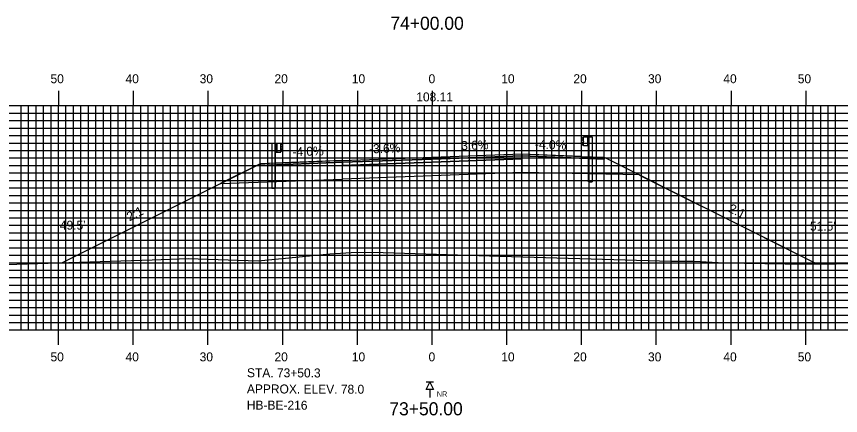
# Model space of a CAD drawing. Extents: x 1761004 to 1761347, y 442591 to 442811.
# Drawn here: x 1761114.1 to 1761224.4, y 442647.2 to 442700.6 of the extents above; entities that cross this region are included whole.
import ezdxf

# ---------------------------------------------------------------- set-up
doc = ezdxf.new("R2010")
doc.units = 0
for name, color, linetype in [('ANNOTATION', 7, 'Continuous'), ('BORING - NO REFUSAL', 7, 'Continuous'), ('D_Guardrail_Beam_Lt', 7, 'Continuous'), ('D_Guardrail_Beam_Rt', 7, 'Continuous'), ('D_Roadway_Centerline', 7, 'Continuous'), ('D_Roadway_Centerline_Text', 7, 'Continuous'), ('D_Roadway_Edge_Shoulder', 7, 'Continuous'), ('D_Roadway_Edge_TW', 7, 'Continuous'), ('D_Roadway_Pavement', 7, 'Continuous'), ('D_Roadway_SlopeLines', 7, 'Continuous'), ('D_Roadway_SubGrade', 7, 'Continuous'), ('D_Text_Standard', 7, 'Continuous'), ('H_V ANNOTATION', 7, 'Continuous'), ('MAJOR', 7, 'Continuous'), ('MINOR', 7, 'Continuous'), ('S_Roadway_Centerline', 7, 'Continuous')]:
    doc.layers.add(name, color=color, linetype=linetype)

msp = doc.modelspace()

# ---------------------------------------------------------------- linework, layer by layer
at = {"layer": 'BORING - NO REFUSAL'}
for p, q in [((1761169.91, 442651.67), (1761168.95, 442651.67)), ((1761169.43, 442650.71), (1761169.43, 442649.65))]:
    msp.add_line(p, q, dxfattribs=at)
msp.add_lwpolyline([(1761169.43, 442651.67), (1761169.91, 442650.71), (1761168.95, 442650.71)], close=True, dxfattribs=at)
at = {"layer": 'D_Guardrail_Beam_Lt'}
for p, q in [((1761148.3, 442683.61), (1761148.3, 442677.61)), ((1761148.77, 442683.61), (1761148.3, 442683.61)), ((1761149.46, 442683.61), (1761148.77, 442683.61)), ((1761148.77, 442683.61), (1761148.77, 442682.44)), ((1761148.83, 442683.61), (1761148.83, 442682.44)), ((1761148.94, 442683.61), (1761148.94, 442682.44)), ((1761149.46, 442682.44), (1761149.46, 442683.61)), ((1761149.46, 442683.53), (1761149.53, 442683.51)), ((1761149.46, 442683.06), (1761149.46, 442682.99)), ((1761149.69, 442683.26), (1761149.49, 442683.13)), ((1761149.49, 442682.93), (1761149.69, 442682.79)), ((1761149.55, 442683.51), (1761149.69, 442683.41)), ((1761148.77, 442682.44), (1761149.46, 442682.44)), ((1761148.79, 442677.61), (1761148.79, 442682.44)), ((1761149.53, 442682.54), (1761149.46, 442682.53)), ((1761149.69, 442682.65), (1761149.55, 442682.55)), ((1761148.79, 442677.61), (1761148.3, 442677.61))]:
    msp.add_line(p, q, dxfattribs=at)
for centre, major_axis, start_param, end_param in [((1761149.54, 442683.06), (-0.0789, 0), 5.323254, 6.283185), ((1761149.54, 442682.99), (-0.0789, 0), 6.283185, 7.243116), ((1761149.52, 442683.47), (0.0417, 0), 0.959931, 1.376053), ((1761149.64, 442683.34), (0.0877, 0), 5.323254, 7.243116), ((1761149.52, 442682.58), (0.0417, 0), 4.907132, 5.323254), ((1761149.64, 442682.72), (0.0877, 0), 5.323254, 7.243116)]:
    msp.add_ellipse(centre, major_axis=major_axis, ratio=0.995501, start_param=start_param, end_param=end_param, dxfattribs=at)
at = {"layer": 'D_Guardrail_Beam_Rt'}
for p, q in [((1761189.91, 442684.37), (1761189.76, 442684.27)), ((1761189.76, 442684.13), (1761189.96, 442683.99)), ((1761190, 442684.39), (1761189.92, 442684.38)), ((1761190, 442684.48), (1761190.69, 442684.48)), ((1761190, 442683.31), (1761190, 442684.48)), ((1761190.52, 442684.48), (1761190.52, 442683.31)), ((1761190.62, 442684.48), (1761190.62, 442683.31)), ((1761190.69, 442684.48), (1761191.16, 442684.48)), ((1761190.69, 442684.48), (1761190.69, 442683.31)), ((1761191.16, 442684.48), (1761191.16, 442678.48)), ((1761189.96, 442683.79), (1761189.76, 442683.66)), ((1761189.76, 442683.51), (1761189.91, 442683.41)), ((1761189.92, 442683.41), (1761190, 442683.39)), ((1761189.99, 442683.93), (1761189.99, 442683.86)), ((1761190.69, 442683.31), (1761190, 442683.31)), ((1761190.66, 442678.48), (1761190.66, 442683.31)), ((1761190.66, 442678.48), (1761191.16, 442678.48))]:
    msp.add_line(p, q, dxfattribs=at)
for centre, major_axis, start_param, end_param in [((1761189.81, 442684.2), (-0.0877, 0), 5.323254, 7.243116), ((1761189.93, 442684.34), (-0.0417, 0), 4.907132, 5.323254), ((1761189.81, 442683.59), (-0.0877, 0), 5.323254, 7.243116), ((1761189.93, 442683.45), (-0.0417, 0), 0.959931, 1.376053), ((1761189.91, 442683.93), (0.0789, 0), 0, 0.959931), ((1761189.91, 442683.86), (0.0789, 0), 5.323254, 6.283185)]:
    msp.add_ellipse(centre, major_axis=major_axis, ratio=0.995501, start_param=start_param, end_param=end_param, dxfattribs=at)
at = {"layer": 'D_Roadway_Centerline'}
msp.add_lwpolyline([(1761120.24, 442667.66), (1761120.72, 442667.91), (1761141.42, 442678.25), (1761141.43, 442678.26), (1761141.44, 442678.26), (1761145.72, 442680.4), (1761146.73, 442680.91), (1761147.95, 442680.96), (1761149.73, 442681.03), (1761149.73, 442681.03), (1761157.1, 442681.32), (1761157.73, 442681.35), (1761169.73, 442681.78), (1761169.73, 442681.78), (1761181.73, 442682.21), (1761181.73, 442682.21), (1761189.63, 442681.9), (1761189.73, 442681.89), (1761192.73, 442681.77), (1761192.73, 442681.77), (1761197.48, 442679.4), (1761197.49, 442679.39), (1761214.48, 442670.9), (1761221.22, 442667.52), (1761221.23, 442667.52)], dxfattribs=at)
at = {"layer": 'D_Roadway_Edge_Shoulder'}
for points in [[(1761181.73, 442682.21), (1761189.73, 442681.89), (1761189.73, 442681.89), (1761192.73, 442681.77), (1761192.73, 442681.52), (1761181.73, 442681.96)], [(1761157.73, 442681.35), (1761149.73, 442681.03), (1761149.73, 442681.03), (1761146.73, 442680.91), (1761146.73, 442680.66), (1761157.73, 442681.1)]]:
    msp.add_lwpolyline(points, close=True, dxfattribs=at)
at = {"layer": 'D_Roadway_Edge_TW'}
msp.add_lwpolyline([(1761157.73, 442681.1), (1761157.73, 442681.35), (1761169.73, 442681.78), (1761181.73, 442682.21), (1761181.73, 442681.96), (1761169.73, 442681.53)], close=True, dxfattribs=at)
at = {"layer": 'D_Roadway_Pavement'}
msp.add_lwpolyline([(1761157.73, 442680.68), (1761157.73, 442681.1), (1761169.73, 442681.53), (1761181.73, 442681.96), (1761181.73, 442681.55), (1761169.73, 442681.11)], close=True, dxfattribs=at)
for points in [[(1761181.73, 442681.96), (1761181.73, 442681.55)], [(1761157.73, 442681.1), (1761157.73, 442680.68)]]:
    msp.add_lwpolyline(points, dxfattribs=at)
at = {"layer": 'D_Roadway_SlopeLines'}
for points in [[(1761146.73, 442680.91), (1761120.24, 442667.66)], [(1761192.73, 442681.77), (1761221.23, 442667.52)]]:
    msp.add_lwpolyline(points, dxfattribs=at)
at = {"layer": 'D_Roadway_SubGrade'}
for points in [[(1761157.73, 442678.85), (1761157.73, 442681.1), (1761157.73, 442680.68), (1761169.73, 442681.11), (1761181.73, 442681.55), (1761181.73, 442681.96), (1761181.73, 442679.71), (1761169.73, 442679.28)], [(1761181.73, 442681.55), (1761181.73, 442681.96), (1761192.73, 442681.52), (1761192.73, 442681.77), (1761197.48, 442679.4), (1761181.73, 442679.71)], [(1761157.73, 442680.68), (1761157.73, 442681.1), (1761146.73, 442680.66), (1761146.73, 442680.91), (1761141.43, 442678.26), (1761157.73, 442678.85)]]:
    msp.add_lwpolyline(points, close=True, dxfattribs=at)
at = {"layer": 'MAJOR'}
for p, q in [((1761119.73, 442690.67), (1761119.73, 442688.67)), ((1761129.73, 442690.67), (1761129.73, 442688.67)), ((1761139.73, 442690.67), (1761139.73, 442688.67)), ((1761149.73, 442690.67), (1761149.73, 442688.67)), ((1761159.73, 442690.67), (1761159.73, 442688.67)), ((1761169.73, 442690.67), (1761169.73, 442688.67)), ((1761179.73, 442690.67), (1761179.73, 442688.67)), ((1761189.73, 442690.67), (1761189.73, 442688.67)), ((1761199.73, 442690.67), (1761199.73, 442688.67)), ((1761209.73, 442690.67), (1761209.73, 442688.67)), ((1761219.73, 442690.67), (1761219.73, 442688.67)), ((1761029.73, 442688.67), (1761309.73, 442688.67)), ((1761029.73, 442688.67), (1761309.73, 442688.67)), ((1761119.73, 442658.67), (1761119.73, 442688.67)), ((1761129.73, 442658.67), (1761129.73, 442688.67)), ((1761139.73, 442658.67), (1761139.73, 442688.67)), ((1761149.73, 442658.67), (1761149.73, 442688.67)), ((1761159.73, 442658.67), (1761159.73, 442688.67)), ((1761169.73, 442658.67), (1761169.73, 442688.67)), ((1761179.73, 442658.67), (1761179.73, 442688.67)), ((1761189.73, 442658.67), (1761189.73, 442688.67)), ((1761199.73, 442658.67), (1761199.73, 442688.67)), ((1761209.73, 442658.67), (1761209.73, 442688.67)), ((1761219.73, 442658.67), (1761219.73, 442688.67)), ((1761029.73, 442683.67), (1761309.73, 442683.67)), ((1761029.73, 442678.67), (1761309.73, 442678.67)), ((1761029.73, 442673.67), (1761309.73, 442673.67)), ((1761029.73, 442668.67), (1761309.73, 442668.67)), ((1761029.73, 442663.67), (1761309.73, 442663.67)), ((1761029.73, 442658.67), (1761309.73, 442658.67)), ((1761029.73, 442658.67), (1761309.73, 442658.67)), ((1761119.73, 442656.66), (1761119.73, 442658.67)), ((1761129.73, 442656.66), (1761129.73, 442658.67)), ((1761139.73, 442656.66), (1761139.73, 442658.67)), ((1761149.73, 442656.66), (1761149.73, 442658.67)), ((1761159.73, 442656.66), (1761159.73, 442658.67)), ((1761169.73, 442656.66), (1761169.73, 442658.67)), ((1761179.73, 442656.66), (1761179.73, 442658.67)), ((1761189.73, 442656.66), (1761189.73, 442658.67)), ((1761199.73, 442656.66), (1761199.73, 442658.67)), ((1761209.73, 442656.66), (1761209.73, 442658.67)), ((1761219.73, 442656.66), (1761219.73, 442658.67))]:
    msp.add_line(p, q, dxfattribs=at)
at = {"layer": 'MINOR'}
for p, q in [((1761114.73, 442658.67), (1761114.73, 442688.67)), ((1761115.73, 442658.67), (1761115.73, 442688.67)), ((1761116.73, 442658.67), (1761116.73, 442688.67)), ((1761117.73, 442658.67), (1761117.73, 442688.67)), ((1761118.73, 442658.67), (1761118.73, 442688.67)), ((1761120.73, 442658.67), (1761120.73, 442688.67)), ((1761121.73, 442658.67), (1761121.73, 442688.67)), ((1761122.73, 442658.67), (1761122.73, 442688.67)), ((1761123.73, 442658.67), (1761123.73, 442688.67)), ((1761124.73, 442658.67), (1761124.73, 442688.67)), ((1761125.73, 442658.67), (1761125.73, 442688.67)), ((1761126.73, 442658.67), (1761126.73, 442688.67)), ((1761127.73, 442658.67), (1761127.73, 442688.67)), ((1761128.73, 442658.67), (1761128.73, 442688.67)), ((1761130.73, 442658.67), (1761130.73, 442688.67)), ((1761131.73, 442658.67), (1761131.73, 442688.67)), ((1761132.73, 442658.67), (1761132.73, 442688.67)), ((1761133.73, 442658.67), (1761133.73, 442688.67)), ((1761134.73, 442658.67), (1761134.73, 442688.67)), ((1761135.73, 442658.67), (1761135.73, 442688.67)), ((1761136.73, 442658.67), (1761136.73, 442688.67)), ((1761137.73, 442658.67), (1761137.73, 442688.67)), ((1761138.73, 442658.67), (1761138.73, 442688.67)), ((1761140.73, 442658.67), (1761140.73, 442688.67)), ((1761141.73, 442658.67), (1761141.73, 442688.67)), ((1761142.73, 442658.67), (1761142.73, 442688.67)), ((1761143.73, 442658.67), (1761143.73, 442688.67)), ((1761144.73, 442658.67), (1761144.73, 442688.67)), ((1761145.73, 442658.67), (1761145.73, 442688.67)), ((1761146.73, 442658.67), (1761146.73, 442688.67)), ((1761147.73, 442658.67), (1761147.73, 442688.67)), ((1761148.73, 442658.67), (1761148.73, 442688.67)), ((1761150.73, 442658.67), (1761150.73, 442688.67)), ((1761151.73, 442658.67), (1761151.73, 442688.67)), ((1761152.73, 442658.67), (1761152.73, 442688.67)), ((1761153.73, 442658.67), (1761153.73, 442688.67)), ((1761154.73, 442658.67), (1761154.73, 442688.67)), ((1761155.73, 442658.67), (1761155.73, 442688.67)), ((1761156.73, 442658.67), (1761156.73, 442688.67)), ((1761157.73, 442658.67), (1761157.73, 442688.67)), ((1761158.73, 442658.67), (1761158.73, 442688.67)), ((1761160.73, 442658.67), (1761160.73, 442688.67)), ((1761161.73, 442658.67), (1761161.73, 442688.67)), ((1761162.73, 442658.67), (1761162.73, 442688.67)), ((1761163.73, 442658.67), (1761163.73, 442688.67)), ((1761164.73, 442658.67), (1761164.73, 442688.67)), ((1761165.73, 442658.67), (1761165.73, 442688.67)), ((1761166.73, 442658.67), (1761166.73, 442688.67)), ((1761167.73, 442658.67), (1761167.73, 442688.67)), ((1761168.73, 442658.67), (1761168.73, 442688.67)), ((1761170.73, 442658.67), (1761170.73, 442688.67)), ((1761171.73, 442658.67), (1761171.73, 442688.67)), ((1761172.73, 442658.67), (1761172.73, 442688.67)), ((1761173.73, 442658.67), (1761173.73, 442688.67)), ((1761174.73, 442658.67), (1761174.73, 442688.67)), ((1761175.73, 442658.67), (1761175.73, 442688.67)), ((1761176.73, 442658.67), (1761176.73, 442688.67)), ((1761177.73, 442658.67), (1761177.73, 442688.67)), ((1761178.73, 442658.67), (1761178.73, 442688.67)), ((1761180.73, 442658.67), (1761180.73, 442688.67)), ((1761181.73, 442658.67), (1761181.73, 442688.67)), ((1761182.73, 442658.67), (1761182.73, 442688.67)), ((1761183.73, 442658.67), (1761183.73, 442688.67)), ((1761184.73, 442658.67), (1761184.73, 442688.67)), ((1761185.73, 442658.67), (1761185.73, 442688.67)), ((1761186.73, 442658.67), (1761186.73, 442688.67)), ((1761187.73, 442658.67), (1761187.73, 442688.67)), ((1761188.73, 442658.67), (1761188.73, 442688.67)), ((1761190.73, 442658.67), (1761190.73, 442688.67)), ((1761191.73, 442658.67), (1761191.73, 442688.67)), ((1761192.73, 442658.67), (1761192.73, 442688.67)), ((1761193.73, 442658.67), (1761193.73, 442688.67)), ((1761194.73, 442658.67), (1761194.73, 442688.67)), ((1761195.73, 442658.67), (1761195.73, 442688.67)), ((1761196.73, 442658.67), (1761196.73, 442688.67)), ((1761197.73, 442658.67), (1761197.73, 442688.67)), ((1761198.73, 442658.67), (1761198.73, 442688.67)), ((1761200.73, 442658.67), (1761200.73, 442688.67)), ((1761201.73, 442658.67), (1761201.73, 442688.67)), ((1761202.73, 442658.67), (1761202.73, 442688.67)), ((1761203.73, 442658.67), (1761203.73, 442688.67)), ((1761204.73, 442658.67), (1761204.73, 442688.67)), ((1761205.73, 442658.67), (1761205.73, 442688.67)), ((1761206.73, 442658.67), (1761206.73, 442688.67)), ((1761207.73, 442658.67), (1761207.73, 442688.67)), ((1761208.73, 442658.67), (1761208.73, 442688.67)), ((1761210.73, 442658.67), (1761210.73, 442688.67)), ((1761211.73, 442658.67), (1761211.73, 442688.67)), ((1761212.73, 442658.67), (1761212.73, 442688.67)), ((1761213.73, 442658.67), (1761213.73, 442688.67)), ((1761214.73, 442658.67), (1761214.73, 442688.67)), ((1761215.73, 442658.67), (1761215.73, 442688.67)), ((1761216.73, 442658.67), (1761216.73, 442688.67)), ((1761217.73, 442658.67), (1761217.73, 442688.67)), ((1761218.73, 442658.67), (1761218.73, 442688.67)), ((1761220.73, 442658.67), (1761220.73, 442688.67)), ((1761221.73, 442658.67), (1761221.73, 442688.67)), ((1761222.73, 442658.67), (1761222.73, 442688.67)), ((1761223.73, 442658.67), (1761223.73, 442688.67)), ((1761029.73, 442687.67), (1761309.73, 442687.67)), ((1761029.73, 442686.67), (1761309.73, 442686.67)), ((1761029.73, 442685.67), (1761309.73, 442685.67)), ((1761029.73, 442684.67), (1761309.73, 442684.67)), ((1761029.73, 442682.67), (1761309.73, 442682.67)), ((1761029.73, 442681.67), (1761309.73, 442681.67)), ((1761029.73, 442680.67), (1761309.73, 442680.67)), ((1761029.73, 442679.67), (1761309.73, 442679.67)), ((1761029.73, 442677.67), (1761309.73, 442677.67)), ((1761029.73, 442676.67), (1761309.73, 442676.67)), ((1761029.73, 442675.67), (1761309.73, 442675.67)), ((1761029.73, 442674.67), (1761309.73, 442674.67)), ((1761029.73, 442672.67), (1761309.73, 442672.67)), ((1761029.73, 442671.67), (1761309.73, 442671.67)), ((1761029.73, 442670.67), (1761309.73, 442670.67)), ((1761029.73, 442669.67), (1761309.73, 442669.67)), ((1761029.73, 442667.67), (1761309.73, 442667.67)), ((1761029.73, 442666.67), (1761309.73, 442666.67)), ((1761029.73, 442665.67), (1761309.73, 442665.67)), ((1761029.73, 442664.67), (1761309.73, 442664.67)), ((1761029.73, 442662.67), (1761309.73, 442662.67)), ((1761029.73, 442661.67), (1761309.73, 442661.67)), ((1761029.73, 442660.67), (1761309.73, 442660.67)), ((1761029.73, 442659.67), (1761309.73, 442659.67))]:
    msp.add_line(p, q, dxfattribs=at)
at = {"layer": 'S_Roadway_Centerline'}
msp.add_lwpolyline([(1761112.76, 442667.42), (1761132.26, 442668.06), (1761137.09, 442668.21), (1761146.47, 442667.93), (1761156.04, 442668.87), (1761158.91, 442669.03), (1761161.73, 442669.09), (1761166.01, 442668.96), (1761178.82, 442668.52), (1761184.88, 442668.34), (1761201.68, 442667.87), (1761204.81, 442667.89), (1761208.81, 442667.63), (1761216.98, 442667.53), (1761223.79, 442667.52), (1761227.64, 442667.57)], dxfattribs=at)

# ---------------------------------------------------------------- texts
at = {"layer": 'ANNOTATION'}
for s, rotation, p in [('3.6%', 2.0618, (1761173.64, 442682.72)), ('-4.0%', 357.7094, (1761183.47, 442682.94)), ('-4.0%', 2.2904, (1761151.05, 442681.88)), ('-3.6%', 2.0618, (1761161.31, 442682.28)), ('2:1', 333.4349, (1761209.29, 442674.53)), ('2:1', 26.5653, (1761129.22, 442673.19))]:
    msp.add_text(s, height=1.2, rotation=rotation, dxfattribs=at).set_placement(p)
at = {"layer": 'BORING - NO REFUSAL'}
for s, p in [('STA. 73+50.3', (1761144.95, 442652.35)), ('APPROX. ELEV. 78.0', (1761144.94, 442650.19)), ('HB-BE-216', (1761144.93, 442648.03))]:
    msp.add_text(s, height=1.2, rotation=359.8142, dxfattribs=at).set_placement(p)
msp.add_text('NR', height=0.7, dxfattribs=at).set_placement((1761170.36, 442649.75))
at = {"layer": 'D_Roadway_Centerline'}
for s, p in [('C', (1761169.72, 442681.78)), ('L', (1761169.73, 442681.77))]:
    msp.add_text(s, height=0.0146, dxfattribs=at).set_placement(p)
at = {"layer": 'D_Roadway_Centerline_Text'}
msp.add_text('108.11', height=1.2, dxfattribs=at).set_placement((1761167.61, 442689.24))
at = {"layer": 'D_Text_Standard'}
for s, p in [("49.5'", (1761119.91, 442672.09)), ("51.5'", (1761220.29, 442671.96))]:
    msp.add_text(s, height=1.2, dxfattribs=at).set_placement(p)
at = {"layer": 'H_V ANNOTATION'}
for s, height, p in [('74+00.00', 1.75, (1761164.14, 442698.82)), ('50', 1.2, (1761118.66, 442691.67)), ('40', 1.2, (1761128.7, 442691.67)), ('30', 1.2, (1761138.62, 442691.67)), ('20', 1.2, (1761148.63, 442691.67)), ('10', 1.2, (1761158.98, 442691.67)), ('0', 1.2, (1761169.25, 442691.67)), ('10', 1.2, (1761178.98, 442691.67)), ('20', 1.2, (1761188.63, 442691.67)), ('30', 1.2, (1761198.62, 442691.67)), ('40', 1.2, (1761208.7, 442691.67)), ('50', 1.2, (1761218.66, 442691.67)), ('50', 1.2, (1761118.66, 442654.47)), ('40', 1.2, (1761128.7, 442654.47)), ('30', 1.2, (1761138.62, 442654.47)), ('20', 1.2, (1761148.63, 442654.47)), ('10', 1.2, (1761158.98, 442654.47)), ('0', 1.2, (1761169.25, 442654.47)), ('10', 1.2, (1761178.98, 442654.47)), ('20', 1.2, (1761188.63, 442654.47)), ('30', 1.2, (1761198.62, 442654.47)), ('40', 1.2, (1761208.7, 442654.47)), ('50', 1.2, (1761218.66, 442654.47)), ('73+50.00', 1.75, (1761164, 442647.25))]:
    msp.add_text(s, height=height, dxfattribs=at).set_placement(p)

doc.saveas('drawing.dxf')
